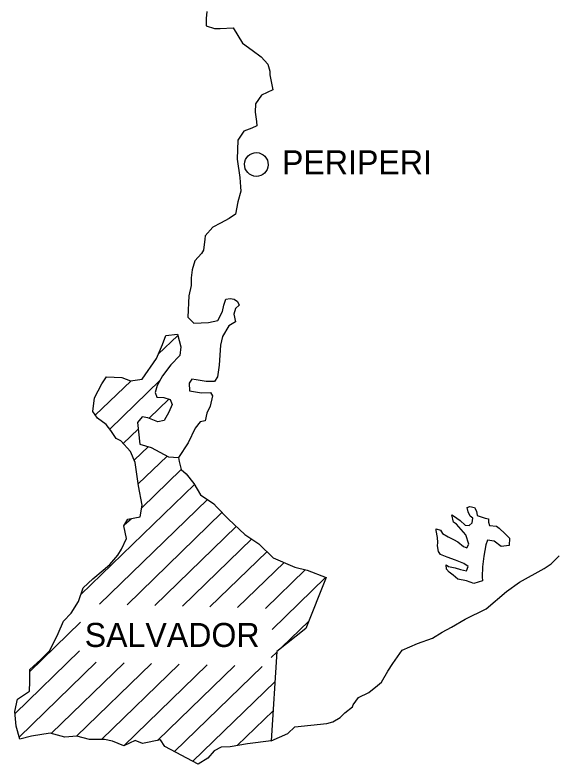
# Model space of a CAD drawing. Extents: x 662444 to 1640468, y 7452018 to 9606170.
# Drawn here: x 1202267 to 1217413, y 8551745 to 8572624 of the extents above; entities that cross this region are included whole.
import ezdxf

# ---------------------------------------------------------------- set-up
doc = ezdxf.new("R2010")
doc.units = 0
for name, color, linetype in [('Level 1', 7, 'Continuous'), ('Level 2', 7, 'Continuous'), ('Level 3', 7, 'Continuous')]:
    doc.layers.add(name, color=color, linetype=linetype)

msp = doc.modelspace()

# ---------------------------------------------------------------- linework, layer by layer
at = {"layer": 'Level 1'}
for points in [[(1207622, 8572721), (1207595, 8572521), (1207601, 8572320), (1207828, 8572248), (1207992, 8572244), (1208353, 8572268), (1208615, 8571838), (1208883, 8571642), (1209130, 8571458), (1209321, 8571253), (1209371, 8571062), (1209379, 8570951), (1209456, 8570537), (1209146, 8570389), (1208976, 8570148), (1208970, 8569915), (1209007, 8569658), (1209015, 8569535), (1208872, 8569472), (1208651, 8569389), (1208481, 8569137), (1208467, 8568603), (1208542, 8568089), (1208557, 8567833), (1208565, 8567710), (1208481, 8567412), (1208417, 8567068), (1208240, 8566950), (1207996, 8566823), (1207786, 8566706), (1207572, 8566466), (1207559, 8566378), (1207529, 8566067), (1207472, 8565979), (1207281, 8565773), (1207209, 8565518), (1207182, 8565296), (1207177, 8565085), (1207115, 8564797), (1207088, 8564197), (1207259, 8564037), (1207663, 8564049), (1207927, 8564109), (1208054, 8564361), (1208091, 8564539), (1208150, 8564704), (1208270, 8564723), (1208379, 8564698), (1208476, 8564640), (1208517, 8564539), (1208416, 8564441), (1208368, 8564287), (1208417, 8564074), (1208229, 8563956), (1208057, 8563660), (1207997, 8563417), (1207961, 8562861), (1207920, 8562539), (1207829, 8562408), (1207600, 8562403), (1207317, 8562455), (1207197, 8562469), (1207129, 8562359), (1207134, 8562148), (1207472, 8562094), (1207723, 8562099), (1207775, 8562009), (1207713, 8561721), (1207621, 8561523), (1207572, 8561313), (1207429, 8561283), (1207294, 8561108), (1207098, 8560702), (1206825, 8560286), (1206844, 8560174), (1206904, 8559950), (1207043, 8559835), (1207254, 8559562), (1207442, 8559246), (1207818, 8559002), (1207892, 8558911), (1208222, 8558569), (1208681, 8558145), (1209067, 8557879), (1209472, 8557491), (1210076, 8557230), (1210413, 8557144), (1210942, 8556941), (1210382, 8555519), (1209569, 8554883), (1209417, 8552394), (1208749, 8552311), (1208267, 8552223), (1208015, 8552218), (1207827, 8552112), (1207647, 8551905), (1207381, 8551745), (1206444, 8552237), (1206329, 8552418), (1205824, 8552319)], [(1205824, 8552319), (1205619, 8552402), (1205299, 8552255), (1204985, 8552385), (1204768, 8552424), (1204342, 8552424), (1203996, 8552522), (1203657, 8552497), (1203245, 8552608), (1202730, 8552521), (1202400, 8552440), (1202300, 8552799), (1202267, 8553212), (1202341, 8553555), (1202674, 8553780), (1202681, 8554047), (1202679, 8554381), (1202992, 8554662), (1203238, 8554912), (1203469, 8555385), (1203619, 8555726), (1203832, 8555954), (1204037, 8556272), (1204167, 8556658), (1204435, 8556907), (1204725, 8557145), (1204915, 8557307), (1205140, 8557568), (1205242, 8557732), (1205381, 8558029), (1205303, 8558388), (1205417, 8558574), (1205756, 8558632), (1205819, 8558964), (1205713, 8559501), (1205620, 8560149), (1205486, 8560453), (1205221, 8560749), (1205092, 8560819), (1204945, 8561046), (1204807, 8561205), (1204571, 8561389), (1204434, 8561571), (1204487, 8561948), (1204694, 8562343), (1204819, 8562540), (1205244, 8562519), (1205493, 8562423), (1205811, 8562471), (1206218, 8563050), (1206381, 8563436), (1206475, 8563689), (1206803, 8563725), (1206893, 8563378), (1206865, 8563134), (1206618, 8562873), (1206381, 8562568), (1206232, 8562293), (1206173, 8562105), (1206224, 8561970), (1206420, 8561965), (1206593, 8561905), (1206655, 8561770), (1206562, 8561550), (1206425, 8561320), (1206250, 8561280), (1205969, 8561398), (1205817, 8561424), (1205682, 8561261), (1205754, 8560658), (1206068, 8560572), (1206552, 8560304), (1206825, 8560286)], [(1206265, 8563172), (1206813, 8563692)], [(1204807, 8562519), (1204830, 8562540)], [(1204508, 8561469), (1205504, 8562423)], [(1204913, 8561080), (1206312, 8562447)], [(1206012, 8561386), (1206561, 8561917)], [(1205285, 8560681), (1205699, 8561082)], [(1205589, 8560217), (1205992, 8560596)], [(1205704, 8559557), (1206509, 8560327)], [(1205807, 8558887), (1206904, 8559950)], [(1204107, 8556470), (1207275, 8559539)], [(1204620, 8556203), (1207636, 8559118)], [(1215347, 8557539), (1215306, 8557240), (1215299, 8556962), (1215307, 8556850), (1215065, 8556779), (1214860, 8556851), (1214621, 8556901), (1214492, 8557005), (1214375, 8557097), (1214300, 8557177), (1214293, 8557300), (1214357, 8557253), (1214541, 8557215), (1214693, 8557167), (1214856, 8557129), (1214903, 8557250), (1214785, 8557331), (1214558, 8557426), (1214320, 8557510), (1214136, 8557582), (1214084, 8557672), (1214055, 8557829), (1214057, 8557918), (1214050, 8558063), (1214011, 8558253), (1214013, 8558298), (1214132, 8558261), (1214195, 8558170), (1214345, 8558077), (1214496, 8558007), (1214615, 8557937), (1214775, 8557810), (1214873, 8557774), (1214930, 8557873), (1214838, 8558132), (1214711, 8558280), (1214584, 8558428), (1214498, 8558485), (1214448, 8558687), (1214502, 8558663), (1214685, 8558536), (1214823, 8558399), (1214932, 8558396), (1215022, 8558472), (1215036, 8558594), (1214961, 8558652), (1214909, 8558775), (1214880, 8558899), (1214957, 8558919), (1215087, 8558893), (1215139, 8558792), (1215158, 8558669), (1215385, 8558596), (1215472, 8558583), (1215470, 8558483), (1215500, 8558393), (1215696, 8558377), (1215771, 8558319), (1215942, 8558159), (1216059, 8558044), (1216053, 8557833), (1215823, 8557805), (1215631, 8557955), (1215446, 8557982), (1215399, 8557850), (1215347, 8557539)], [(1205314, 8558410), (1205504, 8558583)], [(1205395, 8556183), (1208041, 8558752)], [(1206164, 8556163), (1208435, 8558363)], [(1206939, 8556143), (1208874, 8558018)], [(1207703, 8556124), (1209291, 8557662)], [(1209417, 8552394), (1209881, 8552593), (1210071, 8552778), (1210969, 8552877), (1211133, 8552917), (1211333, 8553046), (1211468, 8553176), (1211679, 8553337), (1211702, 8553392), (1211850, 8553600), (1212137, 8553737), (1212382, 8553931), (1212494, 8554029), (1212666, 8554336), (1212802, 8554544), (1213063, 8554916), (1213493, 8555105), (1213912, 8555250), (1214178, 8555421), (1214444, 8555559), (1214821, 8555783), (1215407, 8556068), (1215976, 8556555), (1216343, 8556812), (1217030, 8557195), (1217219, 8557324), (1217444, 8557552)], [(1208477, 8556104), (1209774, 8557360)], [(1209252, 8556084), (1210358, 8557156)], [(1209442, 8555499), (1210931, 8556941)], [(1202677, 8554325), (1204095, 8555695)], [(1209702, 8554991), (1210464, 8555729)], [(1202277, 8553156), (1204070, 8554897)], [(1209417, 8554715), (1209568, 8554861)], [(1202380, 8552496), (1204536, 8554586)], [(1203277, 8552596), (1205311, 8554566)], [(1203985, 8552522), (1206074, 8554546)], [(1204681, 8552426), (1206849, 8554526)], [(1205299, 8552255), (1207623, 8554507)], [(1206241, 8552398), (1208398, 8554487)], [(1206713, 8552096), (1209161, 8554467)], [(1207230, 8551827), (1209514, 8554039)], [(1208464, 8552263), (1209471, 8553227)], [(1209395, 8552394), (1209418, 8552416)]]:
    msp.add_lwpolyline(points, dxfattribs=at)
at = {"layer": 'Level 2'}
msp.add_ellipse((1208999, 8568456), major_axis=(330, -8), ratio=0.999997, dxfattribs=at)

# ---------------------------------------------------------------- texts
at = {"layer": 'Level 3'}
for s, height, p in [('PERIPERI', 670.2, (1209713, 8568182)), ('SALVADOR', 669.8, (1204211, 8555008))]:
    msp.add_text(s, height=height, dxfattribs=at).set_placement(p)

doc.saveas('drawing.dxf')
